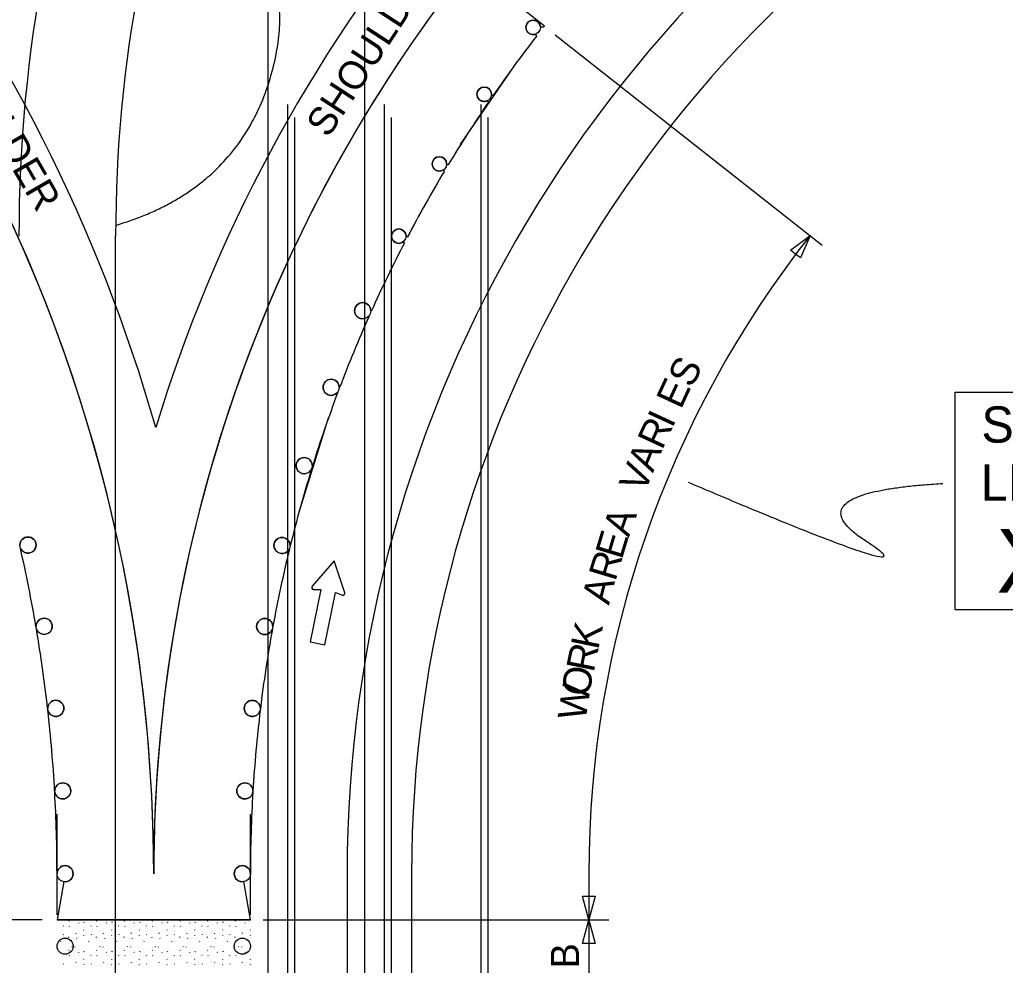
# Model space of a CAD drawing. Extents: x 16715 to 19504, y 7040 to 8495.
# Drawn here: x 16934 to 17178.6, y 7762.8 to 7997.5 of the extents above; entities that cross this region are included whole.
import ezdxf

# ---------------------------------------------------------------- set-up
doc = ezdxf.new("R2010")
doc.units = 0
for name, color, linetype in [('ALI_LEGAL_EX', 7, 'Continuous'), ('MT_SCRATCH_LEVEL_A', 7, 'Continuous'), ('MT_SCRATCH_LEVEL_E', 7, 'Continuous'), ('PAVT_EDGE_EX', 7, 'Continuous'), ('TRAFFIC_SIGNS_PR', 7, 'Continuous'), ('TYPICAL_TEXT_DIMEN_PR', 7, 'Continuous')]:
    doc.layers.add(name, color=color, linetype=linetype)

msp = doc.modelspace()

# ---------------------------------------------------------------- linework, layer by layer
at = {"layer": 'ALI_LEGAL_EX'}
for p, q in [((16995.53, 8241.3), (16995.53, 7423.16)), ((17019.53, 8241.3), (17019.53, 7423.16)), ((17000.51, 7366.28), (17000.51, 7976.48)), ((17024.51, 7366.28), (17024.51, 7976.48)), ((17048.51, 7366.28), (17048.51, 7976.48)), ((17002.26, 7363.06), (17002.26, 7973.25)), ((17026.26, 7363.06), (17026.26, 7973.25)), ((17050.26, 7363.06), (17050.26, 7973.25)), ((16957.79, 7333.59), (16957.79, 7943.78))]:
    msp.add_line(p, q, dxfattribs=at)
for points in [[(17043.31, 7966.45), (17057.43, 7987.09)], [(17003.17, 7874.81), (17010.62, 7898.67)], [(16943.24, 7775.32), (16943.24, 7800.32)], [(16991.24, 7775.32), (16991.24, 7800.32)]]:
    msp.add_lwpolyline(points, dxfattribs=at)
for radius in [364, 340]:
    msp.add_arc((17297.79, 7943.78), radius, 137.516, 180, dxfattribs=at)
at = {"layer": 'MT_SCRATCH_LEVEL_A'}
for p, q in [((16991.24, 7774.07), (16943.24, 7774.07)), ((16943.24, 7774.07), (16991.24, 7774.07)), ((16991.24, 7774.07), (16943.24, 7774.07)), ((16944.74, 7772.61), (16944.79, 7772.53)), ((16946.19, 7773.74), (16946.24, 7773.85)), ((16946.27, 7772.47), (16946.32, 7772.39)), ((16948.56, 7773.29), (16948.61, 7773.21)), ((16949.84, 7771.55), (16949.89, 7771.47)), ((16950.01, 7773.44), (16950.06, 7773.56)), ((16951.63, 7772.61), (16951.68, 7772.53)), ((16953.08, 7773.74), (16953.13, 7773.85)), ((16953.16, 7772.47), (16953.21, 7772.39)), ((16955.45, 7773.29), (16955.5, 7773.21)), ((16956.73, 7771.55), (16956.78, 7771.47)), ((16956.9, 7773.44), (16956.95, 7773.56)), ((16958.52, 7772.61), (16958.57, 7772.53)), ((16959.97, 7773.74), (16960.02, 7773.85)), ((16960.05, 7772.47), (16960.1, 7772.39)), ((16962.34, 7773.29), (16962.39, 7773.21)), ((16963.61, 7771.55), (16963.67, 7771.47)), ((16963.78, 7773.44), (16963.84, 7773.56)), ((16965.4, 7772.61), (16965.46, 7772.53)), ((16966.85, 7773.74), (16966.9, 7773.85)), ((16966.93, 7772.47), (16966.99, 7772.39)), ((16969.22, 7773.29), (16969.28, 7773.21)), ((16970.5, 7771.55), (16970.55, 7771.47)), ((16970.67, 7773.44), (16970.72, 7773.56)), ((16972.29, 7772.61), (16972.34, 7772.53)), ((16973.74, 7773.74), (16973.79, 7773.85)), ((16973.82, 7772.47), (16973.87, 7772.39)), ((16976.11, 7773.29), (16976.16, 7773.21)), ((16977.39, 7771.55), (16977.44, 7771.47)), ((16977.56, 7773.44), (16977.61, 7773.56)), ((16979.18, 7772.61), (16979.23, 7772.53)), ((16980.63, 7773.74), (16980.68, 7773.85)), ((16980.71, 7772.47), (16980.76, 7772.39)), ((16983, 7773.29), (16983.05, 7773.21)), ((16984.28, 7771.55), (16984.33, 7771.47)), ((16984.45, 7773.44), (16984.5, 7773.56)), ((16986.07, 7772.61), (16986.12, 7772.53)), ((16987.52, 7773.74), (16987.57, 7773.85)), ((16987.6, 7772.47), (16987.65, 7772.39)), ((16989.89, 7773.29), (16989.94, 7773.21)), ((16991.16, 7771.55), (16991.22, 7771.47)), ((16944.79, 7770.4), (16944.84, 7770.32)), ((16946.07, 7769.83), (16946.08, 7769.71)), ((16947.91, 7770.68), (16947.96, 7770.8)), ((16948.1, 7769.48), (16948.15, 7769.4)), ((16949.88, 7770.15), (16949.93, 7770.27)), ((16951.68, 7770.4), (16951.73, 7770.32)), ((16952.96, 7769.83), (16952.97, 7769.71)), ((16954.8, 7770.68), (16954.85, 7770.8)), ((16954.99, 7769.48), (16955.04, 7769.4)), ((16956.77, 7770.15), (16956.82, 7770.27)), ((16958.56, 7770.4), (16958.62, 7770.32)), ((16959.85, 7769.83), (16959.86, 7769.71)), ((16961.69, 7770.68), (16961.74, 7770.8)), ((16961.88, 7769.48), (16961.93, 7769.4)), ((16963.66, 7770.15), (16963.71, 7770.27)), ((16965.45, 7770.4), (16965.5, 7770.32)), ((16966.73, 7769.83), (16966.75, 7769.71)), ((16968.58, 7770.68), (16968.63, 7770.8)), ((16968.76, 7769.48), (16968.81, 7769.4)), ((16970.54, 7770.15), (16970.6, 7770.27)), ((16972.34, 7770.4), (16972.39, 7770.32)), ((16973.62, 7769.83), (16973.63, 7769.71)), ((16975.46, 7770.68), (16975.51, 7770.8)), ((16975.65, 7769.48), (16975.7, 7769.4)), ((16977.43, 7770.15), (16977.48, 7770.27)), ((16979.23, 7770.4), (16979.28, 7770.32)), ((16980.51, 7769.83), (16980.52, 7769.71)), ((16982.35, 7770.68), (16982.4, 7770.8)), ((16982.54, 7769.48), (16982.59, 7769.4)), ((16984.32, 7770.15), (16984.37, 7770.27)), ((16986.12, 7770.4), (16986.17, 7770.32)), ((16987.4, 7769.83), (16987.41, 7769.71)), ((16989.24, 7770.68), (16989.29, 7770.8)), ((16989.43, 7769.48), (16989.48, 7769.4)), ((16991.21, 7770.15), (16991.24, 7770.24)), ((16944.17, 7768.65), (16944.22, 7768.77)), ((16946.19, 7766.45), (16946.24, 7766.57)), ((16946.96, 7767.41), (16947.01, 7767.34)), ((16947.69, 7767.38), (16947.74, 7767.31)), ((16951.06, 7768.65), (16951.11, 7768.77)), ((16953.08, 7766.45), (16953.13, 7766.57)), ((16953.84, 7767.41), (16953.89, 7767.34)), ((16954.58, 7767.38), (16954.63, 7767.31)), ((16957.95, 7768.65), (16958, 7768.77)), ((16959.97, 7766.45), (16960.02, 7766.57)), ((16960.73, 7767.41), (16960.78, 7767.34)), ((16961.47, 7767.38), (16961.52, 7767.31)), ((16964.83, 7768.65), (16964.89, 7768.77)), ((16966.85, 7766.45), (16966.9, 7766.57)), ((16967.62, 7767.41), (16967.67, 7767.34)), ((16968.35, 7767.38), (16968.41, 7767.31)), ((16971.72, 7768.65), (16971.77, 7768.77)), ((16973.74, 7766.45), (16973.79, 7766.57)), ((16974.51, 7767.41), (16974.56, 7767.34)), ((16975.24, 7767.38), (16975.29, 7767.31)), ((16978.61, 7768.65), (16978.66, 7768.77)), ((16980.63, 7766.45), (16980.68, 7766.57)), ((16981.39, 7767.41), (16981.44, 7767.34)), ((16982.13, 7767.38), (16982.18, 7767.31)), ((16985.5, 7768.65), (16985.55, 7768.77)), ((16987.52, 7766.45), (16987.57, 7766.57)), ((16988.28, 7767.41), (16988.33, 7767.34)), ((16989.02, 7767.38), (16989.07, 7767.31)), ((16946.27, 7765.19), (16946.32, 7765.11)), ((16948.56, 7766), (16948.61, 7765.93)), ((16949.84, 7764.27), (16949.89, 7764.19)), ((16950.01, 7766.15), (16950.06, 7766.27)), ((16951.63, 7765.33), (16951.68, 7765.25)), ((16953.16, 7765.19), (16953.21, 7765.11)), ((16955.45, 7766), (16955.5, 7765.93)), ((16956.73, 7764.27), (16956.78, 7764.19)), ((16956.9, 7766.15), (16956.95, 7766.27)), ((16958.52, 7765.33), (16958.57, 7765.25)), ((16960.05, 7765.19), (16960.1, 7765.11)), ((16962.34, 7766), (16962.39, 7765.93)), ((16963.61, 7764.27), (16963.67, 7764.19)), ((16963.78, 7766.15), (16963.84, 7766.27)), ((16965.4, 7765.33), (16965.46, 7765.25)), ((16966.93, 7765.19), (16966.99, 7765.11)), ((16969.22, 7766), (16969.28, 7765.93)), ((16970.5, 7764.27), (16970.55, 7764.19)), ((16970.67, 7766.15), (16970.72, 7766.27)), ((16972.29, 7765.33), (16972.34, 7765.25)), ((16973.82, 7765.19), (16973.87, 7765.11)), ((16976.11, 7766), (16976.16, 7765.93)), ((16977.39, 7764.27), (16977.44, 7764.19)), ((16977.56, 7766.15), (16977.61, 7766.27)), ((16979.18, 7765.33), (16979.23, 7765.25)), ((16980.71, 7765.19), (16980.76, 7765.11)), ((16983, 7766), (16983.05, 7765.93)), ((16984.28, 7764.27), (16984.33, 7764.19)), ((16984.45, 7766.15), (16984.5, 7766.27)), ((16986.07, 7765.33), (16986.12, 7765.25)), ((16987.6, 7765.19), (16987.65, 7765.11)), ((16989.89, 7766), (16989.94, 7765.93)), ((16991.16, 7764.27), (16991.22, 7764.19)), ((16944.79, 7763.12), (16944.84, 7763.04)), ((16947.91, 7763.4), (16947.96, 7763.51)), ((16949.88, 7762.87), (16949.93, 7762.98)), ((16951.68, 7763.12), (16951.73, 7763.04)), ((16954.8, 7763.4), (16954.85, 7763.51)), ((16956.77, 7762.87), (16956.82, 7762.98)), ((16958.56, 7763.12), (16958.62, 7763.04)), ((16961.69, 7763.4), (16961.74, 7763.51)), ((16963.66, 7762.87), (16963.71, 7762.98)), ((16965.45, 7763.12), (16965.5, 7763.04)), ((16968.58, 7763.4), (16968.63, 7763.51)), ((16970.54, 7762.87), (16970.6, 7762.98)), ((16972.34, 7763.12), (16972.39, 7763.04)), ((16975.46, 7763.4), (16975.51, 7763.51)), ((16977.43, 7762.87), (16977.48, 7762.98)), ((16979.23, 7763.12), (16979.28, 7763.04)), ((16982.35, 7763.4), (16982.4, 7763.51)), ((16984.32, 7762.87), (16984.37, 7762.98)), ((16986.12, 7763.12), (16986.17, 7763.04)), ((16989.24, 7763.4), (16989.29, 7763.51)), ((16991.21, 7762.87), (16991.24, 7762.95))]:
    msp.add_line(p, q, dxfattribs=at)
for points in [[(17064.2, 7995.96), (17045.35, 8010.82)], [(17063.21, 7995.75), (17064.06, 7995.78)], [(17062.31, 7993.55), (17061.86, 7993.9)], [(17050.35, 7977.08), (17049.92, 7977.37)], [(17051.07, 7979.04), (17051.49, 7978.75)], [(17039.39, 7959.93), (17039, 7960.16)], [(17039.94, 7961.74), (17040.33, 7961.51)], [(17029.88, 7943.81), (17030.24, 7943.62)], [(17029.47, 7942.15), (17029.12, 7942.34)], [(17020.61, 7923.74), (17020.45, 7923.81)], [(17021.11, 7925.3), (17021.27, 7925.23)], [(17013.27, 7906.28), (17013.4, 7906.24)], [(17012.9, 7904.92), (17012.78, 7904.97)], [(17006.59, 7886.83), (17006.68, 7886.8)], [(17006.33, 7885.68), (17006.24, 7885.7)], [(16933.98, 7867.1), (16934.04, 7867.11)], [(17001.09, 7867.01), (17001.15, 7867)], [(16934.23, 7866.25), (16934.18, 7866.23)], [(17000.92, 7866.07), (17000.87, 7866.09)], [(16938.03, 7846.93), (16938.06, 7846.94)], [(16938.17, 7846.28), (16938.14, 7846.28)], [(16996.7, 7846.19), (16996.67, 7846.19)], [(16996.79, 7846.9), (16996.83, 7846.89)], [(16940.92, 7826.57), (16940.94, 7826.57)], [(16940.99, 7826.13), (16940.97, 7826.13)], [(16993.67, 7826.08), (16993.65, 7826.09)], [(16993.71, 7826.56), (16993.73, 7826.56)], [(16942.66, 7806.08), (16942.67, 7806.08)], [(16942.68, 7805.85), (16942.67, 7805.85)], [(16991.85, 7805.84), (16991.84, 7805.84)], [(16991.86, 7806.08), (16991.87, 7806.07)], [(16943.24, 7785.52), (16943.25, 7785.52)], [(16991.24, 7785.52), (16991.24, 7785.52)], [(16944.9, 7783.55), (16943.24, 7774.07), (16991.24, 7774.07), (16989.58, 7783.55)]]:
    msp.add_lwpolyline(points, dxfattribs=at)
for centre, radius, start, end in [((16579.24, 7785.52), 388, 22.8554, 35.7873), ((17331.24, 7785.52), 364, 141.7598, 180), ((17061.41, 7995.64), 1.8, 3.5129, 180), ((17061.41, 7995.64), 1.8, 180, 284.5518), ((17331.24, 7785.52), 340, 141.7598, 141.7992), ((17331.24, 7785.52), 340, 142.2759, 145.3661), ((17049.27, 7979.04), 1.8, 0, 180), ((17331.24, 7785.52), 340, 145.7074, 148.8275), ((17049.27, 7979.04), 1.8, 180, 291.4148), ((17038.14, 7961.74), 1.8, 0, 180), ((17331.24, 7785.52), 340, 149.1383, 152.2895), ((17038.14, 7961.74), 1.8, 180, 298.2766), ((17028.08, 7943.81), 1.8, 0, 180), ((17028.08, 7943.81), 1.8, 180, 305.1374), ((17331.24, 7785.52), 340, 152.5687, 155.7382), ((16579.24, 7785.52), 388, 0, 22.8554), ((16579.24, 7785.52), 388, 0, 22.8554), ((16579.24, 7785.52), 388, 0, 22.8554), ((17331.24, 7785.52), 364, 155.5409, 180), ((17331.24, 7785.52), 364, 155.5409, 180), ((17019.11, 7925.3), 2, 0, 180), ((17331.24, 7785.52), 340, 156.0121, 159.2032), ((17019.11, 7925.3), 2, 180, 312.0242), ((17011.27, 7906.28), 2, 0, 180), ((17011.27, 7906.28), 2, 180, 318.8797), ((17331.24, 7785.52), 340, 159.4399, 162.6687), ((17004.59, 7886.83), 2, 0, 180), ((17004.59, 7886.83), 2, 180, 325.7344), ((17331.24, 7785.52), 340, 162.8672, 166.1345), ((16936.04, 7867.11), 2, 0, 180), ((16936.04, 7867.11), 2, 205.6238, 0), ((16999.09, 7867.01), 2, 0, 180), ((16999.09, 7867.01), 2, 180, 332.5884), ((16579.24, 7785.52), 364, 9.7138, 12.8119), ((17331.24, 7785.52), 340, 166.2942, 169.6006), ((16940.06, 7846.94), 2, 0, 180), ((16994.79, 7846.9), 2, 0, 180), ((16579.24, 7785.52), 364, 6.476, 9.6087), ((16940.06, 7846.94), 2, 199.2175, 0), ((16994.79, 7846.9), 2, 180, 339.4418), ((17331.24, 7785.52), 340, 169.7209, 173.067), ((16942.94, 7826.57), 2, 0, 180), ((16991.71, 7826.56), 2, 0, 180), ((16579.24, 7785.52), 364, 3.238, 6.4057), ((16942.94, 7826.57), 2, 192.8115, 0), ((16991.71, 7826.56), 2, 180, 346.2947), ((17331.24, 7785.52), 340, 173.1474, 176.5334), ((16944.67, 7806.08), 2, 0, 180), ((16944.67, 7806.08), 2, 186.4057, 0), ((16579.24, 7785.52), 364, 0, 3.2028), ((16989.86, 7806.08), 2, 0, 180), ((16989.86, 7806.08), 2, 180, 353.1474), ((17331.24, 7785.52), 340, 176.5737, 180), ((16945.25, 7785.52), 2, 0, 180), ((16989.24, 7785.52), 2, 0, 180), ((16945.25, 7785.52), 2, 260.0595, 0), ((16989.24, 7785.52), 2, 180, 279.941)]:
    msp.add_arc(centre, radius, start, end, dxfattribs=at)
at = {"layer": 'MT_SCRATCH_LEVEL_E'}
for p, q in [((17012.04, 7863.17), (17006.57, 7856.89)), ((17014.67, 7855.25), (17012.04, 7863.17)), ((17008.71, 7856.08), (17006.08, 7843.09)), ((17006.91, 7856.12), (17008.71, 7856.08)), ((17009.75, 7842.34), (17012.38, 7855.33)), ((17012.38, 7855.33), (17014.06, 7854.67)), ((17006.08, 7843.09), (17009.75, 7842.34))]:
    msp.add_line(p, q, dxfattribs=at)
for centre, start, end in [((17006.93, 7856.59), 138.9622, 268.5011), ((17014.22, 7855.11), 248.5735, 18.3105)]:
    msp.add_arc(centre, 0.463, start, end, dxfattribs=at)
at = {"layer": 'PAVT_EDGE_EX'}
for p, q in [((17015.24, 7785.52), (17015.24, 7430.94)), ((17031.24, 7785.52), (17031.24, 7430.94))]:
    msp.add_line(p, q, dxfattribs=at)
for centre, radius, start, end in [((16579.24, 7785.52), 404, 15.917, 59.3713), ((16579.24, 7785.52), 388, 0, 59.3713), ((17331.24, 7785.52), 380, 118.4372, 163.0483), ((17331.24, 7785.52), 364, 118.4372, 180), ((17331.24, 7785.52), 316, 118.4372, 180), ((17331.24, 7785.52), 300, 118.4372, 180), ((17331.24, 7785.52), 300, 180, 180.00000277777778)]:
    msp.add_arc(centre, radius, start, end, dxfattribs=at)
at = {"layer": 'TRAFFIC_SIGNS_PR'}
for p, q in [((17166.19, 7905.08), (17209.39, 7905.08)), ((17166.19, 7851.08), (17166.19, 7905.08)), ((17166.19, 7851.08), (17209.39, 7851.08))]:
    msp.add_line(p, q, dxfattribs=at)
for centre, radius in [((17061.41, 7995.64), 1.8), ((17049.27, 7979.04), 1.8), ((17038.14, 7961.74), 1.8), ((17028.08, 7943.81), 1.8), ((17019.11, 7925.3), 2), ((17011.27, 7906.28), 2), ((17004.59, 7886.83), 2), ((16936.04, 7867.11), 2), ((16999.09, 7867.01), 2), ((16940.06, 7846.94), 2), ((16994.79, 7846.9), 2), ((16942.94, 7826.57), 2), ((16991.71, 7826.56), 2), ((16944.67, 7806.08), 2), ((16989.86, 7806.08), 2), ((16945.25, 7785.52), 2), ((16989.24, 7785.52), 2), ((16945.25, 7767.52), 2), ((16989.24, 7767.52), 2)]:
    msp.add_circle(centre, radius, dxfattribs=at)
at = {"layer": 'TYPICAL_TEXT_DIMEN_PR'}
for p, q in [((17066.91, 7993.83), (17133.18, 7941.61)), ((17125.31, 7940.34), (17130.18, 7943.97)), ((17130.18, 7943.97), (17127.78, 7938.39)), ((17126.55, 7939.37), (17125.31, 7940.34)), ((17127.78, 7938.39), (17126.55, 7939.37)), ((17075.24, 7785.52), (17075.24, 7774.07)), ((17075.24, 7774.07), (17073.67, 7779.93)), ((17073.67, 7779.93), (17075.24, 7779.93)), ((17075.24, 7779.93), (17076.81, 7779.93)), ((17076.81, 7779.93), (17075.24, 7774.07)), ((16939.53, 7774.07), (16854.01, 7774.07)), ((16994.44, 7774.07), (17080.24, 7774.07)), ((17073.67, 7768.21), (17075.24, 7774.07)), ((17075.24, 7774.07), (17075.24, 7751.52)), ((17075.24, 7774.07), (17076.81, 7768.21)), ((17075.24, 7768.21), (17073.67, 7768.21)), ((17076.81, 7768.21), (17075.24, 7768.21))]:
    msp.add_line(p, q, dxfattribs=at)
msp.add_arc((17331.24, 7785.52), 256, 141.7598, 180, dxfattribs=at)
for points in [[(16958.07, 7946.57), (16989.43, 7956), (17004.37, 8015.48), (16951.17, 8021.19), (16951.27, 8096.95), (17001.2, 8100.55)], [(17099.86, 7882.74), (17163.11, 7855.79), (17125.16, 7880.2), (17163.11, 7882.42)]]:
    msp.add_open_spline(points, degree=2, dxfattribs=at)

# ---------------------------------------------------------------- texts
at = {"layer": 'TRAFFIC_SIGNS_PR'}
for s, height, p in [('SPEED', 9, (17172.68, 7892.55)), ('LIMIT', 9, (17172.5, 7878.15)), ('XX', 15.785, (17176.45, 7855.3))]:
    msp.add_text(s, height=height, dxfattribs=at).set_placement(p)
at = {"layer": 'TYPICAL_TEXT_DIMEN_PR'}
for s, rotation, p in [('SHOULDER', 56.8597, (17010.54, 7967.98)), ('SHOULDER', 300.0663, (16912.36, 7994.41)), ('S', 62.4974, (17100.77, 7905.9)), ('E', 65.1772, (17098.08, 7900.6)), ('I', 65.1772, (17095.93, 7895.95)), ('R', 65.1772, (17093.42, 7890.53)), ('A', 67.857, (17091.14, 7884.92)), ('V', 67.857, (17089.04, 7879.77)), ('A', 70.5368, (17085.17, 7868.88)), ('E', 73.2167, (17083.42, 7863.31)), ('R', 73.2167, (17081.79, 7857.91)), ('A', 75.8965, (17080.22, 7852.07)), ('K', 78.5763, (17077.56, 7840.94)), ('R', 78.5763, (17076.43, 7835.3)), ('O', 81.2562, (17075.34, 7829.34)), ('W', 81.2562, (17074.41, 7823.32)), ('B', 90, (17072.81, 7762.03))]:
    msp.add_text(s, height=7, rotation=rotation, dxfattribs=at).set_placement(p)

doc.saveas('drawing.dxf')
